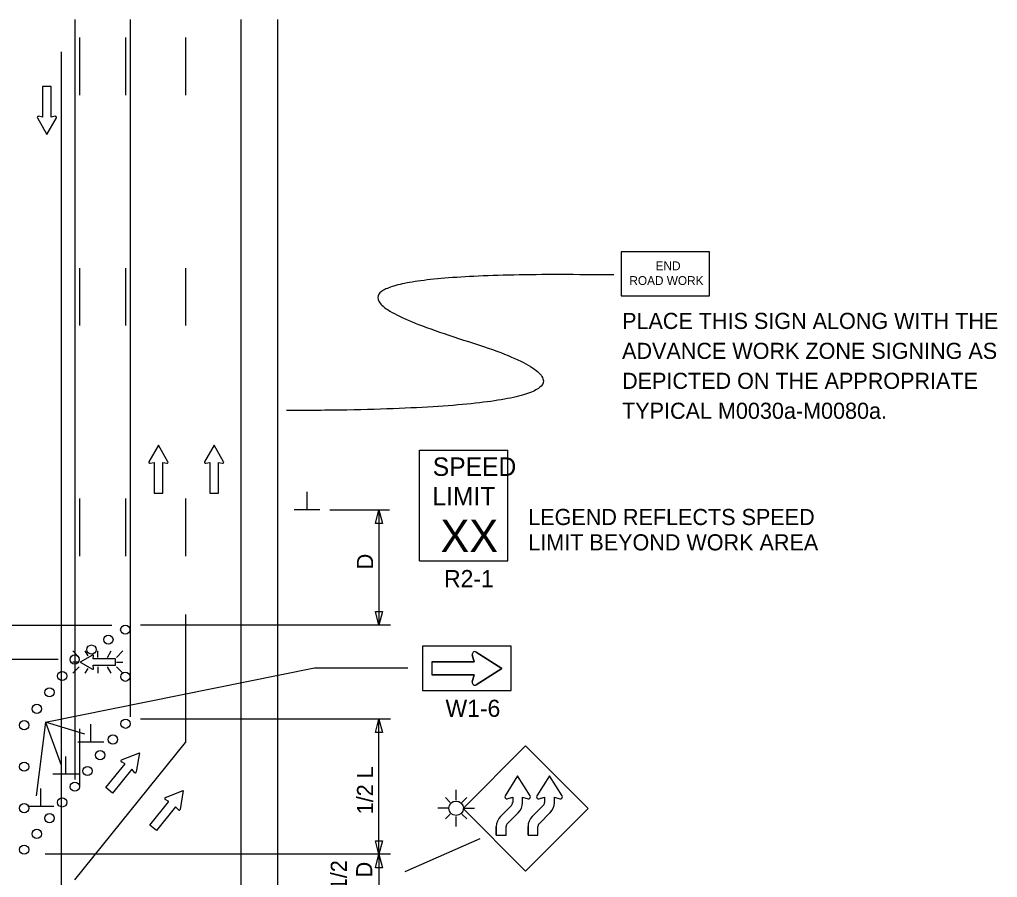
# Model space of a CAD drawing. Extents: x 16525 to 18475, y 5726 to 6926.
# Drawn here: x 16973 to 17397.4, y 6553.8 to 6926.1 of the extents above; entities that cross this region are included whole.
import ezdxf

# ---------------------------------------------------------------- set-up
doc = ezdxf.new("R2010")
doc.units = 0
for name, color, linetype in [('ALI_LEGAL_EX', 7, 'Continuous'), ('MT_SCRATCH_LEVEL_E', 7, 'Continuous'), ('PAVT_EDGE_EX', 7, 'Continuous'), ('TRAFFIC_SIGNS_PR', 7, 'Continuous'), ('TYPICAL_TEXT_DIMEN_PR', 7, 'Continuous')]:
    doc.layers.add(name, color=color, linetype=linetype)

msp = doc.modelspace()

# ---------------------------------------------------------------- linework, layer by layer
at = {"layer": 'ALI_LEGAL_EX'}
for points in [[(16999, 6918.24), (16999, 6893.24)], [(17019, 6918.24), (17019, 6893.24)], [(17045, 6918.24), (17045, 6893.24)], [(16999, 6818.24), (16999, 6793.24)], [(16999, 6818.24), (16999, 6793.24)], [(17019, 6818.24), (17019, 6793.24)], [(17019, 6818.24), (17019, 6793.24)], [(17045, 6818.24), (17045, 6793.24)], [(17045, 6818.24), (17045, 6793.24)], [(16999, 6718.24), (16999, 6693.24)], [(16999, 6718.24), (16999, 6693.24)], [(17019, 6718.24), (17019, 6693.24)], [(17019, 6718.24), (17019, 6693.24)], [(17045, 6718.24), (17045, 6693.24)], [(17045, 6718.24), (17045, 6693.24)], [(16999, 6618.24), (16999, 6593.24)], [(16999, 6618.24), (16999, 6593.24)]]:
    msp.add_lwpolyline(points, dxfattribs=at)
at = {"layer": 'MT_SCRATCH_LEVEL_E'}
for p, q in [((16986.74, 6897.03), (16983, 6897.03)), ((16983, 6897.03), (16983, 6883.77)), ((16986.74, 6897.03), (16983, 6897.03)), ((16983, 6897.03), (16983, 6883.77)), ((16986.74, 6883.77), (16986.74, 6897.03)), ((16986.74, 6883.77), (16986.74, 6897.03)), ((16980.74, 6883.4), (16984.89, 6876.16)), ((16980.74, 6883.4), (16984.89, 6876.16)), ((16983, 6883.77), (16981.22, 6884.09)), ((16983, 6883.77), (16981.22, 6884.09)), ((16984.89, 6876.16), (16989, 6883.4)), ((16984.89, 6876.16), (16989, 6883.4)), ((16988.52, 6884.09), (16986.74, 6883.77)), ((16988.52, 6884.09), (16986.74, 6883.77)), ((17033.24, 6741.41), (17029.13, 6734.17)), ((17033.24, 6741.41), (17029.13, 6734.17)), ((17037.39, 6734.17), (17033.24, 6741.41)), ((17037.39, 6734.17), (17033.24, 6741.41)), ((17057.41, 6741.41), (17053.3, 6734.17)), ((17057.41, 6741.41), (17053.3, 6734.17)), ((17061.56, 6734.17), (17057.41, 6741.41)), ((17061.56, 6734.17), (17057.41, 6741.41)), ((17029.61, 6733.49), (17031.39, 6733.8)), ((17029.61, 6733.49), (17031.39, 6733.8)), ((17031.39, 6733.8), (17031.39, 6720.55)), ((17031.39, 6733.8), (17031.39, 6720.55)), ((17035.13, 6720.55), (17035.13, 6733.8)), ((17035.13, 6733.8), (17036.91, 6733.49)), ((17035.13, 6720.55), (17035.13, 6733.8)), ((17035.13, 6733.8), (17036.91, 6733.49)), ((17053.78, 6733.49), (17055.56, 6733.8)), ((17053.78, 6733.49), (17055.56, 6733.8)), ((17055.56, 6733.8), (17055.56, 6720.55)), ((17055.56, 6733.8), (17055.56, 6720.55)), ((17059.3, 6720.55), (17059.3, 6733.8)), ((17059.3, 6733.8), (17061.08, 6733.49)), ((17059.3, 6720.55), (17059.3, 6733.8)), ((17059.3, 6733.8), (17061.08, 6733.49)), ((17031.39, 6720.55), (17035.13, 6720.55)), ((17031.39, 6720.55), (17035.13, 6720.55)), ((17055.56, 6720.55), (17059.3, 6720.55)), ((17055.56, 6720.55), (17059.3, 6720.55)), ((17017.25, 6604.77), (17025.02, 6607.81)), ((17017.25, 6604.77), (17025.02, 6607.81)), ((17025.02, 6607.81), (17023.68, 6599.59)), ((17025.02, 6607.81), (17023.68, 6599.59)), ((17010.46, 6592.74), (17018.78, 6603.07)), ((17010.46, 6592.74), (17018.78, 6603.07)), ((17021.69, 6600.72), (17013.38, 6590.4)), ((17021.69, 6600.72), (17013.38, 6590.4)), ((17018.78, 6603.07), (17017.19, 6603.94)), ((17018.78, 6603.07), (17017.19, 6603.94)), ((17022.88, 6599.36), (17021.69, 6600.72)), ((17022.88, 6599.36), (17021.69, 6600.72)), ((17013.38, 6590.4), (17010.46, 6592.74)), ((17013.38, 6590.4), (17010.46, 6592.74)), ((17036.29, 6588.46), (17044.06, 6591.49)), ((17036.29, 6588.46), (17044.06, 6591.49)), ((17044.06, 6591.49), (17042.72, 6583.28)), ((17044.06, 6591.49), (17042.72, 6583.28)), ((17037.81, 6586.75), (17036.23, 6587.62)), ((17037.81, 6586.75), (17036.23, 6587.62)), ((17029.5, 6576.43), (17037.81, 6586.75)), ((17029.5, 6576.43), (17037.81, 6586.75)), ((17040.73, 6584.41), (17032.41, 6574.08)), ((17040.73, 6584.41), (17032.41, 6574.08)), ((17041.92, 6583.05), (17040.73, 6584.41)), ((17041.92, 6583.05), (17040.73, 6584.41)), ((17032.41, 6574.08), (17029.5, 6576.43)), ((17032.41, 6574.08), (17029.5, 6576.43))]:
    msp.add_line(p, q, dxfattribs=at)
for centre, start, end in [((16981.15, 6883.63), 80.0362, 209.7731), ((16981.15, 6883.63), 80.0362, 209.7731), ((16988.59, 6883.63), 330.4248, 99.9638), ((16988.59, 6883.63), 330.4248, 99.9638), ((17029.54, 6733.95), 150.4248, 279.9638), ((17029.54, 6733.95), 150.4248, 279.9638), ((17036.98, 6733.95), 260.0362, 29.7731), ((17036.98, 6733.95), 260.0362, 29.7731), ((17053.71, 6733.95), 150.4248, 279.9638), ((17053.71, 6733.95), 150.4248, 279.9638), ((17061.15, 6733.95), 260.0362, 29.7731), ((17061.15, 6733.95), 260.0362, 29.7731), ((17017.43, 6604.34), 111.3861, 241.123), ((17017.43, 6604.34), 111.3861, 241.123), ((17023.22, 6599.67), 221.1954, 350.7344), ((17023.22, 6599.67), 221.1954, 350.7344), ((17036.47, 6588.02), 111.3861, 241.123), ((17036.47, 6588.02), 111.3861, 241.123), ((17042.26, 6583.36), 221.1954, 350.7344), ((17042.26, 6583.36), 221.1954, 350.7344)]:
    msp.add_arc(centre, 0.463, start, end, dxfattribs=at)
at = {"layer": 'PAVT_EDGE_EX'}
for p, q in [((16997, 6926.09), (16997, 6596.31)), ((17021, 6926.09), (17021, 6623.4)), ((17069, 6926.09), (17069, 6062.8)), ((17085, 6926.09), (17085, 6062.8)), ((16991.07, 6912.1), (16991.07, 6082.91)), ((16997, 6871.73), (16997, 6598.71)), ((17021, 6871.73), (17021, 6629.58)), ((17045, 6667.86), (17045, 6612.39)), ((16997, 6552.78), (17045, 6612.39))]:
    msp.add_line(p, q, dxfattribs=at)
at = {"layer": 'TRAFFIC_SIGNS_PR'}
for p, q in [((17146.57, 6739.18), (17184.97, 6739.18)), ((17146.57, 6691.18), (17146.57, 6739.18)), ((17184.97, 6691.18), (17184.97, 6739.18)), ((17146.57, 6691.18), (17184.97, 6691.18)), ((16996.08, 6652.08), (16998.9, 6649.26)), ((17002.8, 6649.89), (17001.54, 6652.08)), ((17006.99, 6649.26), (17006.99, 6652.08)), ((17011.12, 6649.26), (17012.75, 6652.08)), ((17015.07, 6649.26), (17017.89, 6652.08)), ((17171.18, 6651.59), (17182.34, 6644.49)), ((16998.9, 6647.23), (16996.08, 6647.23)), ((17015.07, 6647.23), (17017.89, 6647.23)), ((17151.94, 6647.29), (17170.34, 6647.29)), ((17151.94, 6647.29), (17151.94, 6641.69)), ((17170.34, 6647.29), (17169.5, 6650.35)), ((16996.08, 6642.38), (16998.9, 6645.19)), ((17001.52, 6642.37), (17002.72, 6644.47)), ((17006.99, 6645.19), (17006.99, 6642.37)), ((17012.77, 6642.37), (17011.15, 6645.19)), ((17015.07, 6645.19), (17017.89, 6642.37)), ((17182.34, 6644.49), (17171.18, 6637.39)), ((17170.34, 6641.69), (17151.94, 6641.69)), ((17169.5, 6638.63), (17170.34, 6641.69)), ((17192.62, 6610.85), (17165.47, 6583.7)), ((17219.77, 6583.7), (17192.62, 6610.85)), ((17162.46, 6587.32), (17162.46, 6591.83)), ((17159.94, 6586.28), (17157.84, 6588.39)), ((17164.97, 6586.28), (17167.08, 6588.39)), ((17159.3, 6583.77), (17154.47, 6583.77)), ((17165.47, 6583.7), (17192.62, 6556.55)), ((17165.61, 6583.77), (17170.49, 6583.77)), ((17181.75, 6580.24), (17186.47, 6584.95)), ((17186.47, 6584.95), (17181.75, 6580.24)), ((17192.62, 6556.55), (17219.77, 6583.7)), ((17195.55, 6580.24), (17200.26, 6584.95)), ((17200.26, 6584.95), (17195.55, 6580.24)), ((17159.94, 6581.26), (17157.84, 6579.15)), ((17162.46, 6575.8), (17162.46, 6580.21)), ((17164.97, 6581.26), (17167.08, 6579.15)), ((17184.8, 6577.18), (17189.52, 6581.9)), ((17184.8, 6577.18), (17189.52, 6581.9)), ((17198.6, 6577.18), (17203.31, 6581.9)), ((17198.6, 6577.18), (17203.31, 6581.9)), ((17179.88, 6572.12), (17179.88, 6575.81)), ((17184.2, 6572.12), (17184.2, 6575.81)), ((17193.68, 6572.12), (17193.68, 6575.81)), ((17198, 6572.12), (17198, 6575.81)), ((17179.88, 6572.12), (17184.2, 6572.12)), ((17193.68, 6572.12), (17198, 6572.12))]:
    msp.add_line(p, q, dxfattribs=at)
for points in [[(17234.07, 6806.15), (17272.47, 6806.15), (17272.47, 6825.35), (17234.07, 6825.35)], [(17147.94, 6634.89), (17186.34, 6634.89), (17186.34, 6654.09), (17147.94, 6654.09)]]:
    msp.add_lwpolyline(points, close=True, dxfattribs=at)
for points in [[(17171.18, 6637.39), (17182.34, 6644.49), (17171.18, 6651.59)], [(17004.66, 6650.24), (16999.35, 6647.23), (17004.66, 6644.19)], [(17005.16, 6644.54), (17004.93, 6645.84), (17014.65, 6645.84), (17014.65, 6648.58), (17004.93, 6648.58), (17005.16, 6649.89)], [(17169.5, 6650.35), (17170.34, 6647.29), (17151.94, 6647.29), (17151.94, 6641.69), (17170.34, 6641.69), (17169.5, 6638.63)], [(17194.67, 6589.22), (17189.19, 6597.83), (17183.71, 6589.22)], [(17194.67, 6589.22), (17189.19, 6597.83), (17183.71, 6589.22)], [(17208.47, 6589.22), (17202.99, 6597.83), (17197.5, 6589.22)], [(17208.47, 6589.22), (17202.99, 6597.83), (17197.5, 6589.22)], [(17184.67, 6587.93), (17187.03, 6588.57), (17187.03, 6586.28)], [(17184.67, 6587.92), (17185.5, 6588.15), (17187.03, 6588.57), (17187.03, 6586.28)], [(17191.34, 6586.21), (17191.35, 6588.57), (17193.71, 6587.93)], [(17191.34, 6586.21), (17191.35, 6588.57), (17193.71, 6587.93)], [(17198.46, 6587.93), (17200.83, 6588.57), (17200.82, 6586.28)], [(17198.46, 6587.92), (17199.3, 6588.15), (17200.83, 6588.57), (17200.82, 6586.28)], [(17205.14, 6586.21), (17205.14, 6588.57), (17207.51, 6587.93)], [(17205.14, 6586.21), (17205.14, 6588.57), (17207.51, 6587.93)], [(17179.88, 6575.81), (17179.88, 6572.12), (17184.2, 6572.12), (17184.2, 6575.81)], [(17193.68, 6575.81), (17193.68, 6572.12), (17198, 6572.12), (17198, 6575.81)]]:
    msp.add_lwpolyline(points, dxfattribs=at)
for centre, radius in [((17018.88, 6661.27), 2), ((17011.56, 6656.96), 2), ((17004.23, 6652.65), 2), ((16996.9, 6648.34), 2), ((16991.48, 6641.21), 2), ((17018.94, 6640.87), 2), ((16985.99, 6634.08), 2), ((16980.49, 6626.95), 2), ((16975, 6619.82), 2), ((17019, 6620.47), 2), ((17013.5, 6613.64), 2), ((17008, 6606.81), 2), ((16975, 6601.82), 2), ((17002.5, 6599.98), 2), ((16997, 6593.15), 2), ((16991.5, 6586.32), 2), ((16975, 6583.82), 2), ((17162.46, 6583.77), 3.15), ((16986, 6579.49), 2), ((16980.5, 6572.66), 2), ((16975, 6565.82), 2)]:
    msp.add_circle(centre, radius, dxfattribs=at)
for centre, radius, start, end in [((17170.58, 6650.65), 1.12, 57.5304, 195.3269), ((17170.58, 6650.65), 1.12, 57.5304, 195.3269), ((17004.82, 6649.94), 0.341, 350.7308, 118.8916), ((17004.82, 6644.49), 0.341, 241.4833, 9.9593), ((17170.58, 6638.33), 1.12, 164.6731, 302.4696), ((17170.58, 6638.33), 1.12, 164.6731, 302.4696), ((17184.44, 6588.76), 0.864, 147.5204, 285.3986), ((17184.44, 6588.76), 0.866, 147.5288, 285.3852), ((17193.94, 6588.76), 0.866, 254.6828, 32.2708), ((17193.94, 6588.76), 0.866, 254.6799, 32.2804), ((17190.86, 6577.51), 10.8, 74.68, 74.6808), ((17203.78, 6595.02), 10.8, 212.4569, 212.4665), ((17198.23, 6588.76), 0.864, 147.5204, 285.3986), ((17198.23, 6588.76), 0.866, 147.5288, 285.3852), ((17207.74, 6588.76), 0.866, 254.6828, 32.2708), ((17207.74, 6588.76), 0.866, 254.6799, 32.2804), ((17204.65, 6577.51), 10.8, 74.68, 74.6808), ((17217.58, 6595.02), 10.8, 212.4569, 212.4665), ((17185.17, 6586.28), 1.85, 314.2125, 0), ((17185.17, 6586.28), 1.85, 314.2123, 0.1238), ((17185.17, 6586.28), 6.17, 314.2125, 359.3819), ((17185.17, 6586.28), 6.17, 314.7687, 359.3755), ((17198.97, 6586.28), 1.85, 314.2125, 0), ((17198.97, 6586.28), 1.85, 314.2123, 0.1238), ((17198.97, 6586.28), 6.17, 314.2125, 359.3819), ((17198.97, 6586.28), 6.17, 314.7687, 359.3755), ((17186.05, 6575.82), 6.17, 134.2125, 180), ((17186.05, 6575.82), 6.17, 134.2125, 180), ((17186.05, 6575.82), 6.17, 134.2117, 180), ((17199.85, 6575.82), 6.17, 134.2125, 180), ((17199.85, 6575.82), 6.17, 134.2125, 180), ((17199.85, 6575.82), 6.17, 134.2117, 180), ((17186.05, 6575.82), 1.85, 132.372, 180), ((17186.05, 6575.82), 1.85, 134.2125, 180), ((17199.85, 6575.82), 1.85, 132.372, 180), ((17199.85, 6575.82), 1.85, 134.2125, 180)]:
    msp.add_arc(centre, radius, start, end, dxfattribs=at)
msp.add_open_spline([(17230.88, 6815.23), (17067.17, 6817.61), (17263.08, 6756.87), (17088.82, 6756.35)], degree=2, dxfattribs=at)
at = {"layer": 'TYPICAL_TEXT_DIMEN_PR'}
for p, q in [((17097.76, 6713.27), (17097.76, 6721.06)), ((17103.38, 6713.27), (17092.13, 6713.27)), ((17107.63, 6713.27), (17133.63, 6713.27)), ((17127.43, 6707.41), (17129, 6713.27)), ((17129, 6713.27), (17129, 6663.27)), ((17129, 6713.27), (17130.57, 6707.41)), ((17129, 6707.41), (17127.43, 6707.41)), ((17130.57, 6707.41), (17129, 6707.41)), ((17129, 6663.27), (17127.43, 6669.13)), ((17127.43, 6669.13), (17129, 6669.13)), ((17129, 6669.13), (17130.57, 6669.13)), ((17130.57, 6669.13), (17129, 6663.27)), ((16883.9, 6663.27), (17013.03, 6663.27)), ((17134, 6663.27), (17025.42, 6663.27)), ((16989.81, 6648.35), (16858.32, 6648.35)), ((16984.19, 6621.12), (17101.05, 6644.73)), ((17101.05, 6644.73), (17141.51, 6644.73)), ((16984.19, 6621.12), (16980.18, 6589.12)), ((17001.33, 6616), (16984.19, 6621.12)), ((16984.19, 6621.12), (16991.12, 6602.47)), ((17134, 6622.47), (17025.42, 6622.47)), ((17127.43, 6616.61), (17129, 6622.47)), ((17129, 6563.82), (17129, 6622.47)), ((17129, 6622.47), (17130.57, 6616.61)), ((17003.9, 6612.46), (17003.9, 6620.25)), ((17129, 6616.61), (17127.43, 6616.61)), ((17130.57, 6616.61), (17129, 6616.61)), ((17009.53, 6612.46), (16998.28, 6612.46)), ((16993.08, 6598.54), (16993.08, 6606.32)), ((16998.7, 6598.54), (16987.45, 6598.54)), ((16982.25, 6584.61), (16982.25, 6592.4)), ((16987.87, 6584.61), (16976.62, 6584.61)), ((17172.76, 6570.51), (17140.25, 6556.19)), ((17129, 6563.82), (17127.43, 6569.69)), ((17127.43, 6569.69), (17129, 6569.69)), ((17129, 6569.69), (17130.57, 6569.69)), ((17130.57, 6569.69), (17129, 6563.82)), ((17134, 6563.82), (16984.16, 6563.82)), ((17127.43, 6557.96), (17129, 6563.82)), ((17129, 6563.82), (17130.57, 6557.96)), ((17129, 6563.82), (17129, 6545.42)), ((17129, 6557.96), (17127.43, 6557.96)), ((17130.57, 6557.96), (17129, 6557.96))]:
    msp.add_line(p, q, dxfattribs=at)

# ---------------------------------------------------------------- texts
at = {"layer": 'TRAFFIC_SIGNS_PR'}
for s, height, p in [('END', 3.831, (17249.08, 6817.28)), ('ROAD WORK', 3.831, (17237.68, 6810.89)), ('PLACE THIS SIGN ALONG WITH THE', 7, (17234.51, 6791.8)), ('ADVANCE WORK ZONE SIGNING AS', 7, (17234.51, 6778.8)), ('DEPICTED ON THE APPROPRIATE', 7, (17234.51, 6765.8)), ('TYPICAL M0030a-M0080a.', 7, (17234.51, 6752.8)), ('SPEED', 8, (17152.33, 6728.04)), ('LIMIT', 8, (17152.17, 6715.24)), ('XX', 14.031, (17155.68, 6694.94)), ('R2-1', 7.44, (17157.24, 6679.74)), ('W1-6', 7.44, (17157.88, 6623.45))]:
    msp.add_text(s, height=height, dxfattribs=at).set_placement(p)
at = {"layer": 'TYPICAL_TEXT_DIMEN_PR'}
for s, p in [('LEGEND REFLECTS SPEED', (17193.78, 6706.7)), ('LIMIT BEYOND WORK AREA', (17193.78, 6695.7))]:
    msp.add_text(s, height=7, dxfattribs=at).set_placement(p)
for s, p in [('D', (17126.44, 6687.49)), ('1/2 L', (17126.44, 6581.18)), ('1/2', (17115.07, 6548.23)), ('D', (17126.07, 6553.8))]:
    msp.add_text(s, height=7, rotation=90, dxfattribs=at).set_placement(p)

doc.saveas('drawing.dxf')
